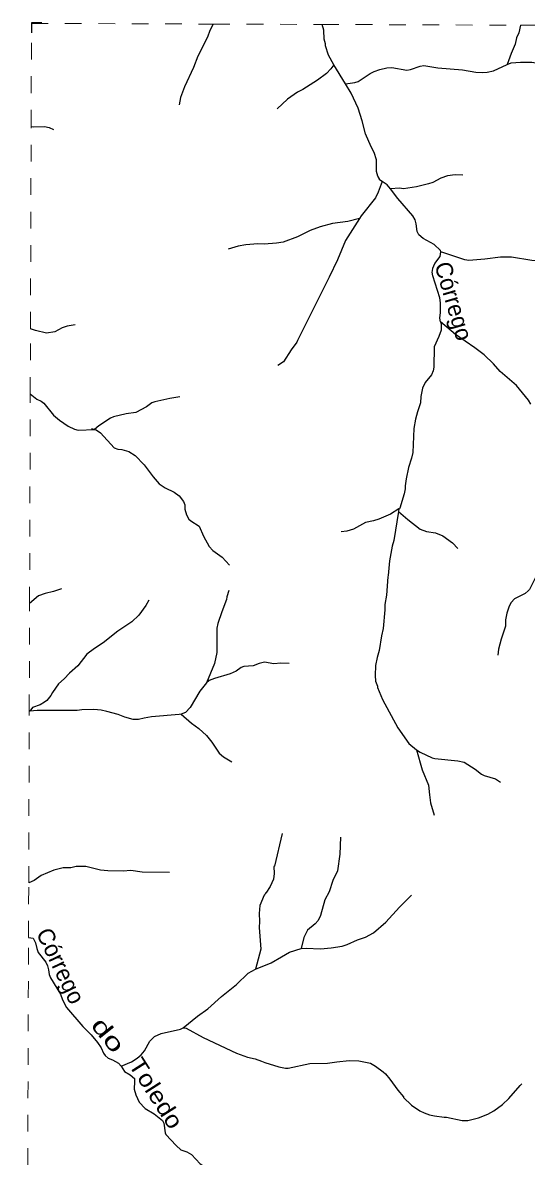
# Model space of a CAD drawing. Extents: x 551.6 to 577.6, y 7567 to 7594.7.
# Drawn here: x 551.65 to 554.66, y 7587.95 to 7594.73 of the extents above; entities that cross this region are included whole.
import ezdxf
from ezdxf.enums import TextEntityAlignment as Align

# ---------------------------------------------------------------- set-up
doc = ezdxf.new("R2010")
doc.units = 0
doc.header["$LTSCALE"] = 0.04
doc.linetypes.add('SHORT_DASHED', pattern=[2.7, 1.5, -1.2])
for name, color, linetype, lineweight in [('53', 7, 'SHORT_DASHED', 13), ('63', 7, 'Continuous', 25), ('7', 7, 'Continuous', 25)]:
    doc.layers.add(name, color=color, linetype=linetype, lineweight=lineweight)
doc.layers.add('61', color=7, linetype='Continuous')

msp = doc.modelspace()

# ---------------------------------------------------------------- linework, layer by layer
at = {"layer": '53'}
msp.add_lwpolyline([(551.6503, 7578.541), (551.6589, 7581.176), (551.6615, 7581.9586), (551.6634, 7582.5573), (551.6645, 7582.8996), (551.6852, 7589.2613), (551.6863, 7589.5882), (551.6896, 7590.6141), (551.6917, 7591.2598), (551.6958, 7592.5139), (551.6971, 7592.9033), (551.701, 7594.113), (551.703, 7594.7296), (552.7903, 7594.7256), (553.4424, 7594.7233), (554.6279, 7594.7189), (556.5859, 7594.7118), (557.3702, 7594.7089), (557.7663, 7594.7075), (559.9893, 7594.6994)], dxfattribs=at)
at = {"layer": '63'}
msp.add_lwpolyline([(551.7649, 7594.734), (551.7033, 7594.734), (551.7033, 7594.6733)], dxfattribs=at)
at = {"layer": '7'}
for points in [[(552.7903, 7594.7256), (552.7707, 7594.6874), (552.7562, 7594.6471), (552.6975, 7594.5328), (552.6725, 7594.4652), (552.6178, 7594.351), (552.5953, 7594.2866), (552.5856, 7594.2423)], [(553.5117, 7594.4812), (553.4797, 7594.5393), (553.4629, 7594.5956), (553.4629, 7594.6069), (553.4548, 7594.6359), (553.4516, 7594.689), (553.4424, 7594.7233)], [(554.6279, 7594.7189), (554.6185, 7594.6729), (554.6057, 7594.6439), (554.5976, 7594.6053), (554.5719, 7594.5489), (554.5486, 7594.4828)], [(554.5486, 7594.4828), (554.5719, 7594.4934), (554.6282, 7594.4974)], [(554.6282, 7594.4974), (554.6958, 7594.4974), (554.8246, 7594.4781), (554.9075, 7594.4507), (555.0065, 7594.3944), (555.1642, 7594.2874), (555.2077, 7594.268), (555.264, 7594.252), (555.3091, 7594.2302), (555.3421, 7594.2077)], [(553.5117, 7594.4812), (553.4942, 7594.4572), (553.4677, 7594.4298), (553.4138, 7594.3896), (553.3261, 7594.334), (553.2947, 7594.3187), (553.2351, 7594.2769), (553.1723, 7594.2182)], [(553.6818, 7594.1465), (553.6568, 7594.2222), (553.6158, 7594.3123), (553.5815, 7594.368), (553.5117, 7594.4812)], [(553.5815, 7594.368), (553.6383, 7594.3751), (553.6576, 7594.3815), (553.7301, 7594.4298), (553.7526, 7594.4411), (553.7864, 7594.454), (553.8299, 7594.4644), (553.8588, 7594.4652), (553.949, 7594.4491), (553.9715, 7594.4531), (554.0278, 7594.4741), (554.0504, 7594.4773), (554.1341, 7594.4636), (554.2822, 7594.4523), (554.361, 7594.4379), (554.3997, 7594.4362), (554.4286, 7594.4379), (554.4673, 7594.4459), (554.5486, 7594.4828)], [(551.701, 7594.113), (551.7165, 7594.1103), (551.7808, 7594.1119), (551.8098, 7594.1063), (551.8348, 7594.0942)], [(553.8016, 7593.783), (553.7848, 7593.794), (553.7848, 7593.7988), (553.7751, 7593.815), (553.7671, 7593.8439), (553.7671, 7593.9131), (553.7542, 7593.9566), (553.7349, 7593.9904), (553.7011, 7594.0693), (553.6818, 7594.1465)], [(554.283, 7593.8214), (554.2371, 7593.823), (554.192, 7593.8174), (554.1518, 7593.8037), (554.1035, 7593.7779), (554.0793, 7593.7691), (554.0069, 7593.7522), (553.9297, 7593.7409), (553.9055, 7593.7433), (553.851, 7593.7409)], [(553.8016, 7593.783), (553.7775, 7593.72), (553.7606, 7593.6854), (553.6753, 7593.5783), (553.6661, 7593.563)], [(553.851, 7593.7409), (553.8314, 7593.7635), (553.8016, 7593.783)], [(554.1517, 7593.3627), (554.1509, 7593.3707), (554.1131, 7593.4069), (554.0455, 7593.4431), (554.0206, 7593.4648), (554.0101, 7593.485), (554.0053, 7593.5301), (553.9989, 7593.555), (553.9844, 7593.5783), (553.8958, 7593.683), (553.851, 7593.7409)], [(553.6661, 7593.563), (553.5949, 7593.5445), (553.5047, 7593.5317), (553.4307, 7593.5123), (553.3711, 7593.4914), (553.2955, 7593.4528), (553.2085, 7593.4214), (553.1699, 7593.4141), (553.0959, 7593.4085), (553.0573, 7593.4109), (552.9848, 7593.4053), (552.9398, 7593.3964), (552.8794, 7593.3788)], [(553.6661, 7593.563), (553.5812, 7593.4303), (553.5329, 7593.316), (553.4838, 7593.2114), (553.2938, 7592.8331)], [(554.1019, 7593.2492), (554.1043, 7593.2645), (554.1155, 7593.2934), (554.1485, 7593.3353), (554.1517, 7593.3627)], [(554.8544, 7593.2999), (554.8294, 7593.2991), (554.6974, 7593.3119), (554.5751, 7593.3321), (554.5091, 7593.3313), (554.4158, 7593.3192), (554.3192, 7593.3111), (554.295, 7593.3144), (554.1517, 7593.3627)], [(554.15, 7592.9437), (554.1453, 7592.9667), (554.1501, 7593.0005), (554.1501, 7593.0584), (554.1469, 7593.0874), (554.1043, 7593.2194), (554.1003, 7593.2419), (554.1019, 7593.2492)], [(554.15, 7592.9437), (554.155, 7592.9321), (554.1534, 7592.8951), (554.1405, 7592.8572), (554.1115, 7592.7937), (554.1099, 7592.6738), (554.1067, 7592.6512), (554.0954, 7592.6263), (554.0576, 7592.582), (554.0423, 7592.5482), (554.0326, 7592.4983), (554.0302, 7592.4597), (554.0117, 7592.4066), (554.0005, 7592.3615), (553.9908, 7592.3052), (553.9836, 7592.1619), (553.9763, 7592.1281), (553.9586, 7592.0718), (553.9441, 7592.0042), (553.9393, 7591.9639)], [(554.6901, 7592.4524), (554.6765, 7592.4749), (554.6057, 7592.5627), (554.5067, 7592.6472), (554.4672, 7592.6931), (554.4109, 7592.747), (554.3546, 7592.7896), (554.2403, 7592.8677), (554.15, 7592.9437)], [(551.9651, 7592.9265), (551.916, 7592.9192), (551.8871, 7592.9087), (551.842, 7592.8846), (551.7937, 7592.8765), (551.7277, 7592.8926), (551.6971, 7592.9033)], [(553.2938, 7592.8331), (553.2914, 7592.8234), (553.2568, 7592.7768), (553.2109, 7592.7059), (553.1772, 7592.6826)], [(551.6958, 7592.5139), (551.7358, 7592.4822), (551.7607, 7592.4701), (551.776, 7592.4581), (551.8355, 7592.3856), (551.8702, 7592.355), (551.9225, 7592.3196), (551.9595, 7592.3011), (551.982, 7592.2971), (552.0806, 7592.2998)], [(552.5906, 7592.4957), (552.5309, 7592.4862), (552.4408, 7592.4653), (552.4239, 7592.4589), (552.3917, 7592.4355), (552.3281, 7592.4017), (552.2702, 7592.3937), (552.1945, 7592.376), (552.1752, 7592.3671), (552.106, 7592.322), (552.0806, 7592.2998)], [(552.0806, 7592.2998), (552.0625, 7592.3035), (552.0899, 7592.2979), (552.1156, 7592.2802), (552.1985, 7592.1909), (552.2203, 7592.1828), (552.2428, 7592.1804), (552.2846, 7592.1691), (552.3241, 7592.1442), (552.378, 7592.0879), (552.4303, 7592.017), (552.4665, 7591.9752), (552.5019, 7591.951), (552.5559, 7591.9253), (552.5872, 7591.9027), (552.613, 7591.869), (552.621, 7591.8504), (552.621, 7591.8239), (552.6307, 7591.7901)], [(553.9393, 7591.9639), (553.9393, 7591.9446), (553.9329, 7591.9156), (553.9063, 7591.8303), (553.9047, 7591.8263), (553.9006, 7591.8255), (553.8997, 7591.8104)], [(552.6307, 7591.7901), (552.6452, 7591.7643), (552.6573, 7591.753), (552.7063, 7591.7209), (552.7321, 7591.6629), (552.7659, 7591.6001), (552.7884, 7591.5768), (552.8431, 7591.5358), (552.8874, 7591.4883)], [(553.9006, 7591.8255), (553.8508, 7591.7933), (553.7816, 7591.7643), (553.7494, 7591.753), (553.7019, 7591.7442), (553.6303, 7591.7048), (553.59, 7591.6927), (553.5554, 7591.6887)], [(553.8997, 7591.8104), (553.8701, 7591.6356), (553.8604, 7591.6018), (553.8459, 7591.5148), (553.8379, 7591.4263), (553.8347, 7591.4183), (553.8266, 7591.3088), (553.817, 7591.2525), (553.817, 7591.2203), (553.8065, 7591.1092), (553.7976, 7591.0658)], [(553.8997, 7591.8104), (553.9538, 7591.7611), (554.0294, 7591.7031), (554.0665, 7591.6895), (554.1196, 7591.6814), (554.1638, 7591.6645), (554.2226, 7591.6227), (554.2532, 7591.5881)], [(555.007, 7591.6931), (554.9976, 7591.6774), (554.9896, 7591.6549), (554.963, 7591.6082), (554.9469, 7591.5864), (554.8986, 7591.5382), (554.8391, 7591.4899), (554.8037, 7591.4673), (554.7562, 7591.4456), (554.7393, 7591.4343), (554.7199, 7591.4167), (554.7135, 7591.407), (554.6821, 7591.3426), (554.6749, 7591.3345), (554.6572, 7591.3193), (554.5936, 7591.2863), (554.5735, 7591.2654), (554.5606, 7591.2428), (554.5477, 7591.201), (554.5397, 7591.1623), (554.5389, 7591.1237), (554.5123, 7591.0464), (554.4978, 7590.9869), (554.493, 7590.9507)], [(551.883, 7591.3466), (551.8356, 7591.3305), (551.7841, 7591.3185), (551.7454, 7591.304), (551.6917, 7591.2598)], [(552.8834, 7591.337), (552.8721, 7591.2992), (552.8705, 7591.2831), (552.8415, 7591.209), (552.8174, 7591.139), (552.811, 7591.1108), (552.811, 7590.966), (552.7981, 7590.9), (552.7506, 7590.7841)], [(552.4046, 7591.279), (552.3876, 7591.2476), (552.345, 7591.1897), (552.3039, 7591.1486), (552.2202, 7591.0931), (552.1317, 7591.0231), (552.0794, 7590.9893), (552.0351, 7590.9555), (551.9796, 7590.8871), (551.9297, 7590.8428), (551.8983, 7590.8082), (551.8653, 7590.7784), (551.8283, 7590.7261), (551.8194, 7590.7084), (551.7953, 7590.6786), (551.7808, 7590.6682)], [(553.7976, 7591.0658), (553.7832, 7590.9772), (553.7711, 7590.937), (553.7622, 7590.8887), (553.759, 7590.8275), (553.7622, 7590.7954), (553.7735, 7590.7648), (553.7735, 7590.7567), (553.8025, 7590.6843), (553.8942, 7590.5145), (553.961, 7590.4219), (554.0056, 7590.3843)], [(553.2448, 7590.9), (553.1941, 7590.9016), (553.1538, 7590.8983), (553.0975, 7590.9072), (553.0653, 7590.9), (553.0299, 7590.8871), (552.9736, 7590.8822), (552.9575, 7590.8766), (552.9269, 7590.8549), (552.8915, 7590.838), (552.7981, 7590.8106), (552.7667, 7590.7977), (552.7506, 7590.7841)], [(552.7506, 7590.7841), (552.7112, 7590.735), (552.6532, 7590.636), (552.6242, 7590.607), (552.598, 7590.5979)], [(551.7808, 7590.6682), (551.7551, 7590.6529), (551.7095, 7590.6372), (551.6936, 7590.6145)], [(552.3764, 7590.5724), (552.3426, 7590.5644), (552.3104, 7590.566), (552.2621, 7590.5796), (552.2219, 7590.5957), (552.1543, 7590.6134), (552.1205, 7590.6207), (552.0754, 7590.6247), (552.0046, 7590.6231), (551.9756, 7590.6191), (551.7374, 7590.6191), (551.6936, 7590.6145), (551.6896, 7590.6141)], [(552.598, 7590.5979), (552.5872, 7590.5941), (552.4215, 7590.5813), (552.3764, 7590.5724)], [(552.598, 7590.5979), (552.6605, 7590.5426), (552.7039, 7590.5105), (552.7498, 7590.4686), (552.7812, 7590.43), (552.8255, 7590.364), (552.8512, 7590.3414), (552.9019, 7590.3117)], [(554.0056, 7590.3843), (554.0278, 7590.3704), (554.1003, 7590.335), (554.1164, 7590.331)], [(554.0056, 7590.3843), (554.0407, 7590.2642), (554.0793, 7590.1724), (554.0834, 7590.1145), (554.0906, 7590.0662), (554.1115, 7589.993)], [(554.1164, 7590.331), (554.2548, 7590.3173), (554.2926, 7590.3092), (554.357, 7590.2682), (554.3948, 7590.2376), (554.4109, 7590.2296), (554.4785, 7590.2102), (554.5099, 7590.1901)], [(553.2021, 7589.8835), (553.157, 7589.6879), (553.1538, 7589.6847), (553.1554, 7589.6445), (553.1506, 7589.6107), (553.1313, 7589.5656), (553.1055, 7589.5253), (553.1023, 7589.5253), (553.0975, 7589.5141), (553.0942, 7589.5133), (553.0685, 7589.4529), (553.0645, 7589.4047), (553.0669, 7589.3564), (553.0645, 7589.321), (553.0749, 7589.1914), (553.0442, 7589.0716)], [(553.5514, 7589.861), (553.5482, 7589.7588), (553.5337, 7589.6606), (553.5055, 7589.601), (553.4846, 7589.5334), (553.4572, 7589.4867), (553.4323, 7589.3918), (553.4178, 7589.3628), (553.4001, 7589.3419), (553.355, 7589.3048), (553.3325, 7589.2614), (553.3159, 7589.1943)], [(552.5285, 7589.6493), (552.3651, 7589.6509), (552.2975, 7589.6614), (552.2525, 7589.6573), (552.1607, 7589.659), (552.1156, 7589.663), (552.0287, 7589.6855), (551.9708, 7589.6863), (551.9386, 7589.6783), (551.8935, 7589.6775), (551.8372, 7589.6638), (551.7615, 7589.6324), (551.7197, 7589.601), (551.6863, 7589.5882)], [(553.3159, 7589.1943), (553.347, 7589.197), (553.4323, 7589.1938), (553.4967, 7589.1986), (553.5611, 7589.2099), (553.5924, 7589.2187), (553.6544, 7589.2469), (553.7011, 7589.2622), (553.7502, 7589.2896), (553.8234, 7589.3523), (553.9047, 7589.4433), (553.9771, 7589.5149)], [(551.6852, 7589.2613), (551.714, 7589.2566), (551.7277, 7589.2292), (551.7341, 7589.1954), (551.7438, 7589.1705), (551.7881, 7589.1133), (551.7985, 7589.0908), (551.805, 7589.0683), (551.8082, 7589.0393), (551.8162, 7589.02), (551.8766, 7588.9218), (551.8879, 7588.888), (551.9128, 7588.8429), (552.011, 7588.7286), (552.0609, 7588.6779), (552.0979, 7588.6337), (552.1204, 7588.5999), (552.1333, 7588.5684), (552.143, 7588.554), (552.1623, 7588.5395), (552.1881, 7588.529), (552.2235, 7588.5081), (552.2401, 7588.4909)], [(553.0442, 7589.0716), (553.1369, 7589.1093), (553.1989, 7589.1455)], [(553.1989, 7589.1455), (553.2472, 7589.1737), (553.3159, 7589.1943)], [(552.6115, 7588.7206), (552.6967, 7588.7898), (552.7571, 7588.834), (552.84, 7588.9089), (552.9293, 7588.9805), (553.0001, 7589.0473), (553.0442, 7589.0716)], [(552.2401, 7588.4909), (552.3023, 7588.5161), (552.3362, 7588.5387), (552.3587, 7588.5588), (552.3796, 7588.5822), (552.4102, 7588.6401), (552.4384, 7588.6691), (552.4794, 7588.6868), (552.5943, 7588.7131), (552.6115, 7588.7206)], [(552.6115, 7588.7206), (552.6281, 7588.7187), (552.7305, 7588.6634), (552.9301, 7588.5684), (552.9945, 7588.5443), (553.0412, 7588.5355), (553.0798, 7588.5218)], [(553.0798, 7588.5218), (553.0991, 7588.5129), (553.1828, 7588.4872), (553.223, 7588.4791), (553.2391, 7588.4791), (553.3679, 7588.5065), (553.4741, 7588.5081), (553.5305, 7588.5177), (553.6029, 7588.5242), (553.6625, 7588.5226), (553.7309, 7588.5081), (553.7622, 7588.492), (553.8065, 7588.4574)], [(552.2401, 7588.4909), (552.2605, 7588.459), (552.2943, 7588.4397), (552.3192, 7588.4172), (552.32, 7588.3987)], [(553.8065, 7588.4574), (553.821, 7588.4453), (553.8475, 7588.4131), (553.895, 7588.3471), (553.9288, 7588.3085), (553.9296, 7588.3029), (553.9763, 7588.2586), (554.027, 7588.2232), (554.052, 7588.2119), (554.0842, 7588.2007), (554.1148, 7588.1942), (554.1727, 7588.1862), (554.1856, 7588.187), (554.2805, 7588.1652), (554.3127, 7588.1669), (554.3771, 7588.1813), (554.4335, 7588.2047)], [(552.32, 7588.3987), (552.3168, 7588.3536), (552.3265, 7588.3198), (552.3466, 7588.2763), (552.3828, 7588.2385), (552.4367, 7588.2063), (552.4874, 7588.1652), (552.4939, 7588.1492), (552.5019, 7588.0928), (552.5075, 7588.0816), (552.5679, 7588.0172), (552.5969, 7587.9906), (552.6323, 7587.9777), (552.6605, 7587.9624), (552.712, 7587.9069), (552.7289, 7587.8964), (552.8218, 7587.8654)], [(554.4335, 7588.2047), (554.4697, 7588.2232), (554.5204, 7588.261), (554.5598, 7588.2981), (554.6258, 7588.3761), (554.6371, 7588.385)]]:
    msp.add_lwpolyline(points, dxfattribs=at)

# ---------------------------------------------------------------- texts
at = {"layer": '61'}
for rotation, p in [(286.339, (554.1811, 7593.0544)), (295.59, (551.8325, 7589.07))]:
    msp.add_text('Córrego', height=0.1, rotation=rotation, dxfattribs=at).set_placement(p, align=Align.CENTER)
for s, rotation, width, p in [('do', 308.637, 1.5, (552.1228, 7588.6467)), ('Toledo', 302.521, 1.15, (552.4064, 7588.3028))]:
    msp.add_text(s, height=0.1, rotation=rotation, dxfattribs=dict(at, width=width)).set_placement(p, align=Align.CENTER)

doc.saveas('drawing.dxf')
